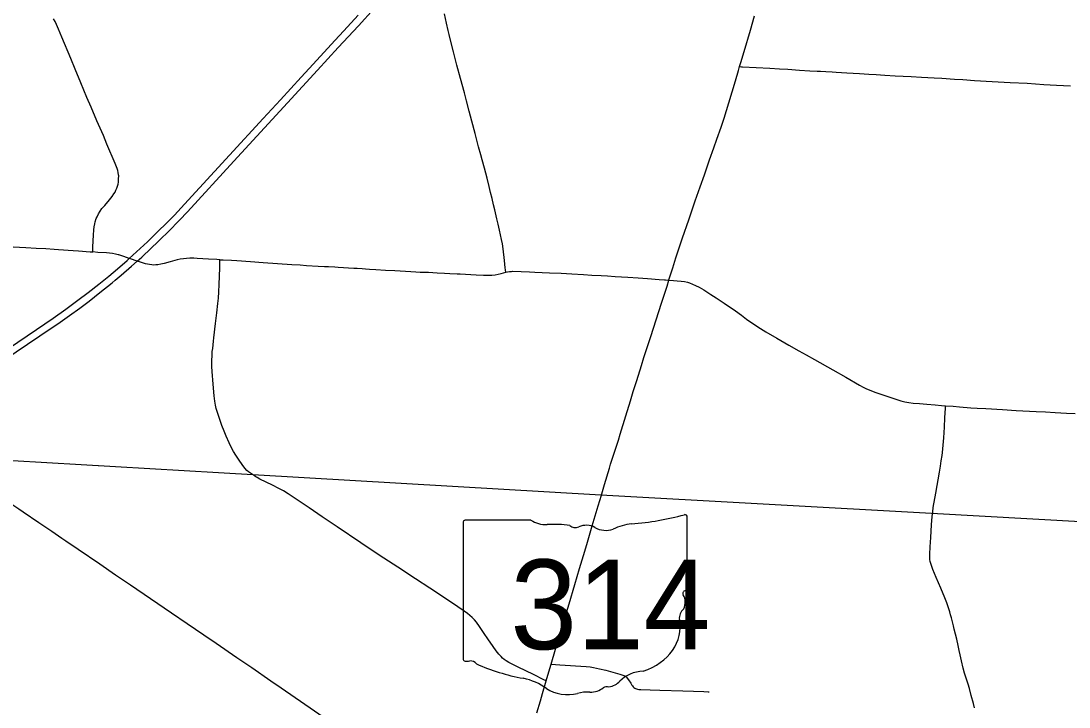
# Model space of a CAD drawing. Extents: x 9078 to 9739, y 4248 to 4966.
# Drawn here: x 9549.3 to 9630.7, y 4525.8 to 4579 of the extents above; entities that cross this region are included whole.
import ezdxf

# ---------------------------------------------------------------- set-up
doc = ezdxf.new("R2010")
doc.units = 0
for name, color, linetype in [('GM_X_County_Road', 7, 'Continuous'), ('GM_X_Interstate_Route', 7, 'Continuous'), ('GM_X_State_Route', 7, 'Continuous'), ('GM_X_State_Shield', 7, 'Continuous'), ('GM_X_Township', 7, 'Continuous'), ('GM_X_Township_Road', 7, 'Continuous')]:
    doc.layers.add(name, color=color, linetype=linetype)

msp = doc.modelspace()

# ---------------------------------------------------------------- linework, layer by layer
at = {"layer": 'GM_X_County_Road'}
for points in [[(9554.883, 4561.11), (9554.885, 4561.507), (9554.927, 4562.408), (9554.959, 4562.817), (9554.988, 4563.061), (9555.03, 4563.303), (9555.07, 4563.462), (9555.148, 4563.696), (9555.211, 4563.847), (9555.322, 4564.066), (9555.45, 4564.276), (9555.595, 4564.475), (9555.805, 4564.727), (9556.179, 4565.162), (9556.381, 4565.42), (9556.523, 4565.621), (9556.608, 4565.761), (9556.683, 4565.907), (9556.748, 4566.057), (9556.801, 4566.212), (9556.84, 4566.372), (9556.867, 4566.534), (9556.889, 4566.779), (9556.891, 4567.025), (9556.886, 4567.106), (9556.861, 4567.268), (9556.821, 4567.427), (9556.77, 4567.583), (9556.617, 4567.964), (9555.982, 4569.476), (9555.701, 4570.159), (9555.203, 4571.284), (9554.748, 4572.337), (9554.422, 4573.09), (9553.964, 4574.232), (9553.523, 4575.292), (9553.174, 4576.124), (9552.478, 4577.788), (9552.225, 4578.394), (9552.063, 4578.77), (9551.954, 4578.991), (9551.832, 4579.204)], [(9548.698, 4561.52), (9549.68, 4561.455), (9550.498, 4561.403), (9551.235, 4561.369), (9551.89, 4561.329), (9552.217, 4561.308), (9553.36, 4561.223), (9553.768, 4561.192), (9554.667, 4561.123), (9554.883, 4561.11)], [(9556.843, 4560.889), (9556.656, 4560.935), (9556.418, 4560.981), (9556.177, 4561.015), (9555.935, 4561.04), (9555.285, 4561.082), (9554.883, 4561.11)], [(9558.496, 4560.349), (9558.337, 4560.402), (9557.82, 4560.577), (9557.717, 4560.612), (9557.28, 4560.758), (9556.891, 4560.877), (9556.843, 4560.889)], [(9564.75, 4560.511), (9564.524, 4560.525), (9563.873, 4560.561), (9562.981, 4560.612), (9562.736, 4560.624), (9562.409, 4560.627), (9562.163, 4560.616), (9561.918, 4560.59), (9561.675, 4560.548), (9561.435, 4560.493), (9560.882, 4560.341), (9560.411, 4560.211), (9560.174, 4560.156), (9559.935, 4560.117), (9559.775, 4560.103), (9559.614, 4560.099), (9559.453, 4560.108), (9559.293, 4560.127), (9559.134, 4560.158), (9558.978, 4560.198), (9558.591, 4560.316), (9558.496, 4560.349)], [(9567.64, 4543.602), (9567.536, 4543.662), (9567.426, 4543.73), (9566.973, 4544.049), (9566.852, 4544.162), (9566.688, 4544.347), (9566.487, 4544.608), (9566.25, 4544.944), (9565.979, 4545.355), (9565.808, 4545.635), (9565.651, 4545.924), (9565.471, 4546.293), (9565.239, 4546.818), (9565.08, 4547.195), (9564.901, 4547.654), (9564.709, 4548.191), (9564.559, 4548.658), (9564.471, 4548.974), (9564.416, 4549.214), (9564.36, 4549.539), (9564.308, 4549.946), (9564.223, 4550.843), (9564.14, 4551.823), (9564.121, 4552.233), (9564.122, 4552.643), (9564.143, 4553.135), (9564.162, 4553.38), (9564.189, 4553.625), (9564.25, 4554.194), (9564.279, 4554.44), (9564.414, 4555.573), (9564.501, 4556.386), (9564.589, 4557.118), (9564.629, 4557.524), (9564.661, 4558.014), (9564.684, 4558.586), (9564.71, 4559.241), (9564.737, 4559.871), (9564.75, 4560.511)], [(9564.75, 4560.511), (9565.004, 4560.5), (9565.661, 4560.466), (9566.07, 4560.438), (9567.134, 4560.365), (9568.116, 4560.29), (9570.327, 4560.139), (9570.982, 4560.103), (9571.474, 4560.074), (9572.373, 4560.016), (9572.864, 4559.986), (9573.191, 4559.971), (9573.683, 4559.957), (9573.929, 4559.944), (9574.336, 4559.913), (9574.743, 4559.886), (9575.151, 4559.861), (9575.396, 4559.849), (9575.804, 4559.825), (9576.049, 4559.808), (9576.376, 4559.787), (9576.867, 4559.753), (9577.603, 4559.706), (9578.341, 4559.665), (9579.159, 4559.611), (9579.567, 4559.583), (9579.975, 4559.56), (9580.301, 4559.546), (9580.957, 4559.533), (9581.614, 4559.503), (9582.187, 4559.466), (9582.596, 4559.445), (9583.169, 4559.422), (9583.415, 4559.409), (9583.825, 4559.391), (9584.234, 4559.371), (9584.644, 4559.349), (9585.218, 4559.319), (9585.626, 4559.309), (9585.871, 4559.317), (9586.114, 4559.341), (9586.354, 4559.382), (9586.593, 4559.438), (9586.954, 4559.532)], [(9586.954, 4559.532), (9587.069, 4559.561), (9587.232, 4559.591), (9587.396, 4559.608), (9587.479, 4559.611), (9588.136, 4559.591), (9588.792, 4559.559), (9589.201, 4559.547), (9590.35, 4559.503), (9591.252, 4559.469), (9592.072, 4559.426), (9592.972, 4559.359), (9593.627, 4559.324), (9594.364, 4559.284), (9594.855, 4559.257), (9595.428, 4559.219), (9596.409, 4559.157), (9597.223, 4559.103), (9597.958, 4559.046), (9598.859, 4558.981), (9599.266, 4558.953), (9599.345, 4558.945), (9599.605, 4558.921)], [(9599.605, 4558.921), (9599.963, 4558.894), (9600.246, 4558.877), (9600.568, 4558.844), (9600.813, 4558.811), (9601.056, 4558.762), (9601.214, 4558.714), (9601.445, 4558.624), (9601.667, 4558.519), (9601.96, 4558.37), (9602.315, 4558.163), (9602.875, 4557.821), (9603.289, 4557.555), (9603.9, 4557.142), (9604.773, 4556.532), (9605.24, 4556.198), (9605.636, 4555.908), (9606.44, 4555.341), (9606.714, 4555.162), (9607.133, 4554.907), (9607.983, 4554.413), (9608.913, 4553.892), (9609.699, 4553.451), (9610.274, 4553.135), (9610.916, 4552.771), (9612.341, 4551.96), (9613.338, 4551.391), (9614.4, 4550.771), (9614.688, 4550.617), (9614.908, 4550.511), (9615.21, 4550.385), (9615.67, 4550.214), (9617.376, 4549.632), (9617.611, 4549.561), (9617.928, 4549.485), (9618.249, 4549.425), (9618.573, 4549.382), (9619.062, 4549.341), (9619.634, 4549.299), (9620.286, 4549.245), (9620.775, 4549.206), (9621.088, 4549.181)], [(9621.088, 4549.181), (9621.673, 4549.134), (9622.163, 4549.091), (9623.06, 4549.02), (9623.551, 4548.993), (9624.205, 4548.952), (9625.508, 4548.88), (9626.564, 4548.82), (9628.118, 4548.738), (9628.855, 4548.698), (9629.589, 4548.651), (9630.487, 4548.6), (9631.142, 4548.568)], [(9590.085, 4527.831), (9589.902, 4527.919), (9589.089, 4528.313), (9587.907, 4528.885), (9587.391, 4529.138), (9587.173, 4529.258), (9586.964, 4529.39), (9586.83, 4529.487), (9586.702, 4529.593), (9586.582, 4529.707), (9586.417, 4529.892), (9586.212, 4530.151), (9585.971, 4530.484), (9585.555, 4531.095), (9585.278, 4531.501), (9584.905, 4532.042), (9584.663, 4532.372), (9584.509, 4532.562), (9584.342, 4532.74), (9584.161, 4532.905), (9583.971, 4533.058), (9583.706, 4533.25), (9583.229, 4533.568), (9582.339, 4534.157), (9581.039, 4535.019), (9579.94, 4535.738), (9578.567, 4536.64), (9577.126, 4537.587), (9575.688, 4538.538), (9573.847, 4539.773), (9572.69, 4540.554), (9571.671, 4541.246), (9571.129, 4541.617), (9570.522, 4542.038), (9570.043, 4542.354), (9569.693, 4542.567), (9569.335, 4542.766), (9568.823, 4543.024), (9567.861, 4543.487), (9567.64, 4543.602)]]:
    msp.add_lwpolyline(points, dxfattribs=at)
at = {"layer": 'GM_X_Interstate_Route'}
for points in [[(9559.93, 4561.899), (9560.124, 4562.085), (9560.755, 4562.711), (9561.617, 4563.577), (9562.239, 4564.23), (9565.845, 4568.155), (9567.621, 4570.087), (9570.005, 4572.685), (9571.172, 4573.952), (9572.339, 4575.219), (9573.945, 4576.975), (9575.5, 4578.665), (9576.72, 4579.994), (9578.326, 4581.748), (9579.382, 4582.895), (9581.767, 4585.493), (9584.577, 4588.549)], [(9546.787, 4552.596), (9550.503, 4555.096), (9551.793, 4555.971), (9552.799, 4556.681), (9553.726, 4557.359), (9554.511, 4557.955), (9555.349, 4558.614), (9556.116, 4559.233), (9556.806, 4559.815), (9557.55, 4560.46), (9557.717, 4560.612), (9558.28, 4561.122), (9559.12, 4561.905), (9559.834, 4562.584), (9560.709, 4563.449), (9561.222, 4563.98), (9562.009, 4564.817), (9565.503, 4568.624), (9568.114, 4571.46), (9569.446, 4572.91), (9571.052, 4574.665), (9571.995, 4575.692), (9573.385, 4577.201), (9574.662, 4578.59), (9575.494, 4579.497)], [(9556.615, 4558.915), (9557.084, 4559.306), (9557.891, 4560.003), (9558.337, 4560.402), (9558.685, 4560.714), (9559.423, 4561.411), (9559.93, 4561.899)], [(9541.67, 4548.503), (9544.786, 4550.609), (9546.94, 4552.031), (9547.987, 4552.726), (9550.776, 4554.606), (9552.34, 4555.659), (9553.078, 4556.179), (9553.874, 4556.757), (9554.594, 4557.3), (9555.435, 4557.955), (9556.392, 4558.728), (9556.615, 4558.915)]]:
    msp.add_lwpolyline(points, dxfattribs=at)
at = {"layer": 'GM_X_State_Route'}
for points in [[(9589.358, 4525.35), (9589.635, 4526.291), (9589.797, 4526.84), (9590.085, 4527.831), (9590.14, 4528.018), (9590.458, 4529.135), (9591.144, 4531.45), (9591.856, 4533.804), (9592.298, 4535.298), (9592.672, 4536.554), (9593.071, 4537.89), (9593.281, 4538.596), (9593.65, 4539.853), (9594.117, 4541.421), (9594.373, 4542.246), (9594.456, 4542.515), (9594.619, 4543.065), (9594.992, 4544.323), (9595.088, 4544.637), (9595.689, 4546.507), (9595.83, 4546.977), (9596.255, 4548.391), (9596.617, 4549.566), (9596.835, 4550.271), (9597.108, 4551.13), (9597.475, 4552.302), (9597.668, 4552.929), (9597.872, 4553.553), (9598.209, 4554.564), (9599.036, 4557.14), (9599.463, 4558.467), (9599.605, 4558.921), (9599.61, 4558.937), (9599.904, 4559.875), (9600.148, 4560.658), (9600.355, 4561.281), (9600.672, 4562.213), (9601.148, 4563.609), (9601.336, 4564.152), (9601.662, 4565.08), (9602.044, 4566.163), (9602.375, 4567.088), (9602.767, 4568.254), (9603.094, 4569.182), (9603.342, 4569.877), (9603.673, 4570.802), (9603.908, 4571.499), (9604.268, 4572.672), (9604.78, 4574.398), (9605.01, 4575.183), (9605.099, 4575.495), (9605.19, 4575.814), (9605.45, 4576.678), (9605.936, 4578.329), (9606.252, 4579.433)], [(9546.283, 4543.115), (9546.679, 4542.848), (9547.832, 4542.065), (9548.985, 4541.281), (9549.13, 4541.182), (9549.48, 4540.945)], [(9549.48, 4540.945), (9550.682, 4540.129), (9551.701, 4539.44), (9552.473, 4538.913)], [(9552.473, 4538.913), (9552.784, 4538.7), (9553.734, 4538.055), (9555.428, 4536.899), (9556.65, 4536.07), (9557.802, 4535.285), (9559.365, 4534.229), (9560.991, 4533.12), (9562.212, 4532.288), (9563.499, 4531.411), (9564.45, 4530.767), (9566.072, 4529.652), (9567.221, 4528.862), (9568.708, 4527.839), (9569.516, 4527.278), (9572.084, 4525.511), (9574.046, 4524.166), (9576.228, 4522.664)]]:
    msp.add_lwpolyline(points, dxfattribs=at)
at = {"layer": 'GM_X_State_Shield'}
for p, q in [((9601.033, 4535.022), (9601.033, 4540.55)), ((9583.631, 4540.106), (9583.631, 4529.54)), ((9588.899, 4540.288), (9583.803, 4540.288)), ((9601.032, 4535.024), (9601.033, 4535.022))]:
    msp.add_line(p, q, dxfattribs=at)
for centre, major_axis, start_param, end_param in [((9594.834, 4554.693), (18.455, 0), 4.814394, 5.042369), ((9600.84, 4540.573), (0.194, 0), 6.141152, 7.989035), ((9583.831, 4540.129), (0.202, 0), 1.712693, 3.28349), ((9590.113, 4541.515), (1.955, 0), 4.042523, 4.731795), ((9590.761, 4534.356), (7.02, 0), 1.404758, 1.657858), ((9592.355, 4540.183), (0.564, 0), 3.836095, 5.185415), ((9593.183, 4538.962), (1.173, 0), 0.950623, 2.079405), ((9594.697, 4540.637), (1.411, 0), 4.081561, 5.145723), ((9597.188, 4537.061), (3.713, 0), 1.699011, 2.107814), ((9600.989, 4534.617), (0.3, 0), 1.883978, 3.671073), ((9600.827, 4535.001), (0.207, 0), 5.05454, 6.418171), ((9599.081, 4533.918), (1.8, 0), 5.934695, 6.695948), ((9601.727, 4532.709), (1.309, 0), 2.387724, 3.262537), ((9595.868, 4532.006), (4.616, 0), 5.101752, 6.440018), ((9583.832, 4529.517), (0.203, 0), 3.00124, 4.508301), ((9583.863, 4530.598), (1.552, 0), 4.665946, 4.897461), ((9584.181, 4528.93), (0.56, 0), 0.519207, 1.627899), ((9591.247, 4538.424), (13.327, 0), 4.195997, 4.488961), ((9597.815, 4526.573), (2.528, 0), 1.647645, 2.488434), ((9587.274, 4524.793), (4.17, 0), 0.823519, 1.323587), ((9594.612, 4528.516), (1.491, 0), 4.937069, 5.64225), ((9591.783, 4528.878), (2.646, 0), 4.026481, 4.996735), ((9593.312, 4525.224), (2.174, 0), 1.495662, 1.94098), ((9593.505, 4528.086), (1.41, 0), 4.691044, 5.507374), ((9594.781, 4527.063), (0.397, 0), 1.147584, 2.315152)]:
    msp.add_ellipse(centre, major_axis=major_axis, ratio=0.8, start_param=start_param, end_param=end_param, dxfattribs=at)
at = {"layer": 'GM_X_Township'}
msp.add_lwpolyline([(9653.666, 4539.22), (9639.912, 4539.697), (9620.004, 4540.807), (9594.322, 4542.244), (9567.304, 4543.805), (9543.295, 4545.207), (9538.415, 4545.532), (9536.932, 4545.613), (9535.939, 4545.668), (9518.307, 4546.633), (9518.835, 4554.998), (9519.363, 4563.373), (9520.243, 4577.33), (9508.475, 4575.726), (9505.121, 4575.269), (9455.38, 4568.492), (9450.392, 4567.812), (9449.713, 4567.764), (9447.057, 4567.406)], dxfattribs=at)
at = {"layer": 'GM_X_Township_Road'}
for points in [[(9586.954, 4559.532), (9586.926, 4559.722), (9586.903, 4559.884), (9586.842, 4560.455), (9586.74, 4561.35), (9586.68, 4561.755), (9586.622, 4562.077), (9586.465, 4562.796), (9586.355, 4563.274), (9586.264, 4563.672), (9586.1, 4564.383), (9586.005, 4564.778), (9585.893, 4565.254), (9585.77, 4565.728), (9585.644, 4566.201), (9585.49, 4566.837), (9585.283, 4567.626), (9585.111, 4568.253), (9584.998, 4568.646), (9584.824, 4569.276), (9584.56, 4570.306), (9584.314, 4571.257), (9584.109, 4572.049), (9583.894, 4572.839), (9583.729, 4573.473), (9583.429, 4574.579), (9583.151, 4575.607), (9582.885, 4576.638), (9582.686, 4577.432), (9582.542, 4577.987), (9582.464, 4578.305), (9582.337, 4578.863), (9582.18, 4579.583)], [(9605.099, 4575.495), (9605.242, 4575.484), (9605.324, 4575.479), (9606.389, 4575.432), (9607.454, 4575.374), (9608.191, 4575.329), (9608.845, 4575.287), (9609.743, 4575.226), (9610.56, 4575.177), (9611.131, 4575.144), (9611.376, 4575.131), (9611.785, 4575.109), (9612.277, 4575.084), (9612.605, 4575.07), (9613.424, 4575.022), (9613.914, 4574.985), (9614.404, 4574.951), (9615.14, 4574.908), (9615.713, 4574.875), (9616.368, 4574.834), (9617.187, 4574.789), (9618.415, 4574.725), (9619.234, 4574.687), (9620.216, 4574.629), (9620.79, 4574.599), (9621.772, 4574.53), (9622.426, 4574.483), (9623.326, 4574.418), (9624.718, 4574.347), (9626.11, 4574.27), (9627.421, 4574.198), (9628.731, 4574.118), (9629.713, 4574.061), (9630.778, 4573.996)], [(9620.089, 4540.936), (9620.135, 4541.27), (9620.328, 4542.4), (9620.612, 4544.014), (9620.697, 4544.498), (9620.761, 4544.902), (9620.817, 4545.308), (9620.846, 4545.551), (9620.904, 4546.121), (9620.949, 4546.692), (9621.003, 4547.509), (9621.043, 4548.245), (9621.078, 4548.982), (9621.088, 4549.181)], [(9623.328, 4525.745), (9623.256, 4526.064), (9623.09, 4526.696), (9622.938, 4527.248), (9622.846, 4527.562), (9622.664, 4528.107), (9622.564, 4528.419), (9622.458, 4528.815), (9622.328, 4529.374), (9622.22, 4529.854), (9622.154, 4530.175), (9622.071, 4530.577), (9621.962, 4531.057), (9621.862, 4531.454), (9621.76, 4531.85), (9621.7, 4532.087), (9621.54, 4532.717), (9621.479, 4532.954), (9621.416, 4533.192), (9621.302, 4533.586), (9621.195, 4533.896), (9621.042, 4534.276), (9620.713, 4535.027), (9620.355, 4535.854), (9620.102, 4536.46), (9620.017, 4536.691), (9619.943, 4536.925), (9619.903, 4537.085), (9619.876, 4537.246), (9619.862, 4537.408), (9619.865, 4537.652), (9619.897, 4538.225), (9619.944, 4538.962), (9620.002, 4539.941), (9620.049, 4540.595), (9620.089, 4540.936)], [(9590.458, 4529.135), (9591.138, 4529.085), (9593.178, 4528.939), (9593.503, 4528.905), (9593.745, 4528.867), (9594.226, 4528.769), (9594.702, 4528.65), (9595.256, 4528.505), (9595.808, 4528.356), (9595.965, 4528.31), (9596.042, 4528.282), (9596.116, 4528.248), (9596.188, 4528.209), (9596.213, 4528.192)], [(9596.213, 4528.192), (9596.256, 4528.163), (9596.317, 4528.11), (9596.372, 4528.05), (9596.467, 4527.917), (9596.645, 4527.643), (9596.731, 4527.504), (9596.78, 4527.438), (9596.833, 4527.376), (9596.893, 4527.321), (9596.959, 4527.272), (9597.03, 4527.232), (9597.105, 4527.201), (9597.184, 4527.179), (9597.264, 4527.165), (9597.427, 4527.152), (9598.163, 4527.133), (9598.9, 4527.116), (9600.697, 4527.057), (9601.514, 4527.029), (9602.331, 4527.003), (9602.658, 4526.988), (9602.739, 4526.984)]]:
    msp.add_lwpolyline(points, dxfattribs=at)

# ---------------------------------------------------------------- texts
at = {"layer": 'GM_X_State_Shield'}
msp.add_text('314', height=6.961, dxfattribs=at).set_placement((9587.3, 4530.285))

doc.saveas('drawing.dxf')
